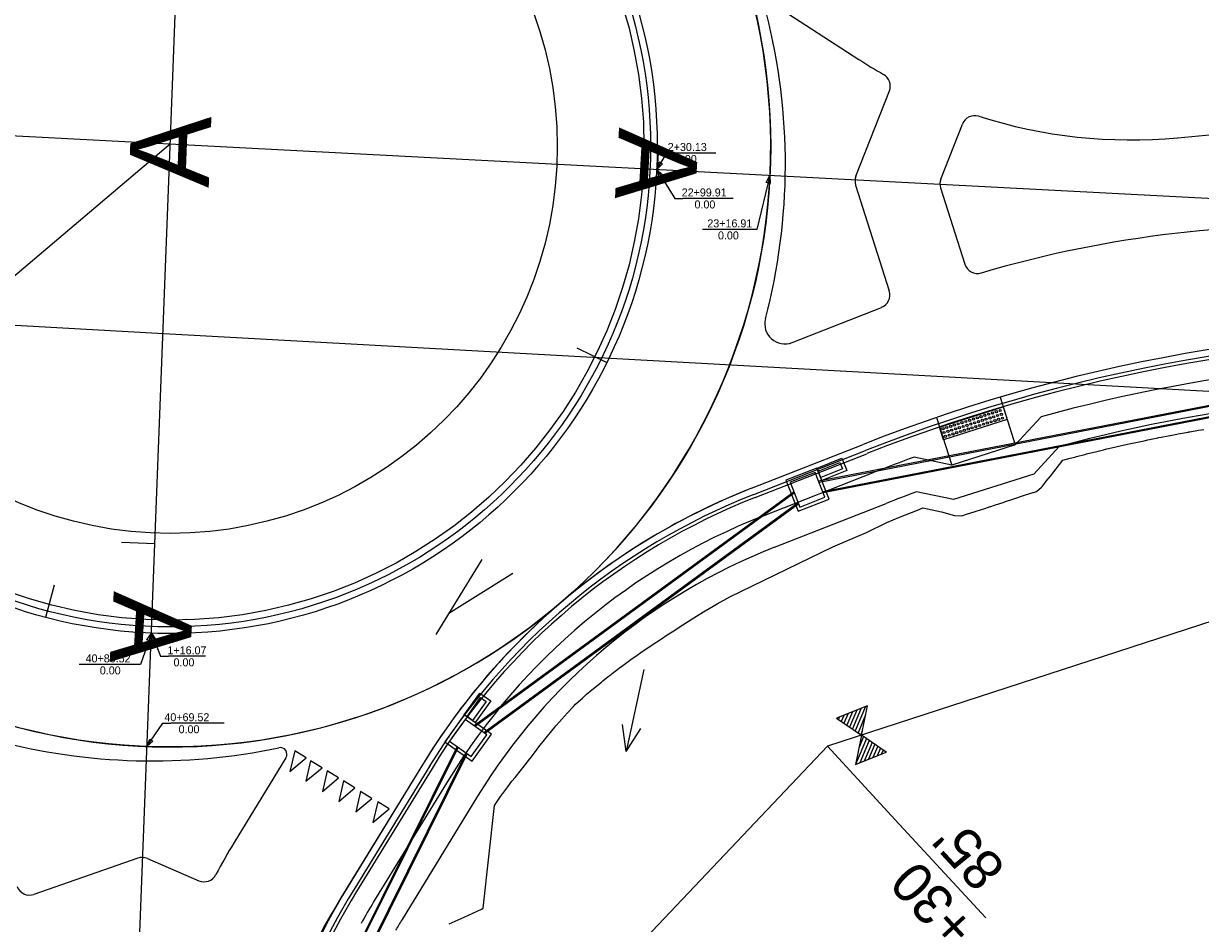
# Model space of a CAD drawing. Extents: x 670017 to 673226, y 705371 to 707498.
# Drawn here: x 671704.7 to 671881.1, y 706424.9 to 706559.8 of the extents above; entities that cross this region are included whole.
import ezdxf

# ---------------------------------------------------------------- set-up
doc = ezdxf.new("R2010")
doc.units = 0
for name, color, linetype in [('EL R 264', 7, 'Continuous'), ('EL R SCBV', 7, 'Continuous'), ('R_Drainage Flow Lines', 7, 'Continuous'), ('R_Drainage Stage 2', 7, 'Continuous'), ('R_Fence', 7, 'Continuous'), ('R_Horz Alg', 7, 'Continuous'), ('R_Horz Alg Annot', 7, 'Continuous'), ('R_Horz Alg Station', 7, 'Continuous'), ('R_No Plot', 7, 'Continuous'), ('R_No Plot FOC', 7, 'Continuous'), ('R_Proposed Const Limits Stage 2', 7, 'Continuous'), ('R_Proposed Median', 7, 'Continuous'), ('R_Proposed RAB', 7, 'Continuous'), ('R_Proposed Road Stage 2', 7, 'Continuous'), ('R_Proposed Sidewalk Stage 2', 7, 'Continuous'), ('R_ROW', 7, 'Continuous'), ('R_ROW Annot', 7, 'Continuous'), ('R_Striping', 7, 'Continuous'), ('R_Water Annot', 7, 'Continuous'), ('S_EXIST_ROW', 7, 'Continuous')]:
    doc.layers.add(name, color=color, linetype=linetype)

# ---------------------------------------------------------------- blocks, each defined once
blk = doc.blocks.new('FLOW ARROW')
at = {"layer": 'R_Water Annot'}
for p, q in [((-12.57, 0), (0, 0)), ((0, 0), (-3.85, 1.4)), ((0, 0), (-3.85, -1.4))]:
    blk.add_line(p, q, dxfattribs=at)

msp = doc.modelspace()

# ---------------------------------------------------------------- linework, layer by layer
at = {"layer": 'EL R 264'}
msp.add_line((671813.85, 706490.13), (671830.58, 706496.71), dxfattribs=at)
for centre, radius, start, end in [((671922.4, 706263.11), 251, 86.9958, 111.4581), ((671850.79, 706396.13), 101, 111.4581, 130.4404), ((671726.73, 706541.35), 90, 220.3024, 310.6243)]:
    msp.add_arc(centre, radius, start, end, dxfattribs=at)
at = {"layer": 'EL R SCBV'}
msp.add_line((671764.69, 706448.93), (671752.31, 706428.73), dxfattribs=at)
for centre, radius, start, end in [((671726.73, 706541.35), 90, 310.6243, 44.214), ((671850.79, 706396.13), 101, 130.4078, 148.4842), ((671838.41, 706375.93), 101, 148.4842, 177.7825)]:
    msp.add_arc(centre, radius, start, end, dxfattribs=at)
at = {"layer": 'R_Drainage Stage 2'}
for p, q in [((671926.49, 706511.08), (671823.91, 706491.17)), ((671926.48, 706510.91), (671823.97, 706491.01)), ((671926.45, 706509.38), (671824.53, 706489.59)), ((671926.44, 706509.2), (671824.59, 706489.44)), ((671820.24, 706489.58), (671772.3, 706454.51)), ((671820.3, 706489.42), (671772.44, 706454.41)), ((671820.87, 706487.97), (671773.73, 706453.49)), ((671820.93, 706487.81), (671773.87, 706453.39)), ((671769.73, 706451.43), (671743.1, 706397.91)), ((671769.86, 706451.33), (671743.27, 706397.88)), ((671771.1, 706450.45), (671744.8, 706397.59)), ((671771.24, 706450.35), (671744.97, 706397.56))]:
    msp.add_line(p, q, dxfattribs=at)
for points in [[(671823.66, 706493.16), (671819.01, 706491.33), (671820.84, 706486.68), (671825.49, 706488.5)], [(671823.67, 706493.16), (671827.38, 706494.64), (671828.12, 706492.78), (671824.4, 706491.3)], [(671823.85, 706492.69), (671827.1, 706493.99), (671827.47, 706493.06), (671824.22, 706491.76)], [(671823.38, 706492.51), (671819.66, 706491.05), (671821.12, 706487.32), (671824.84, 706488.79)], [(671770.8, 706456.19), (671773.13, 706459.44), (671774.76, 706458.28), (671772.43, 706455.03)], [(671771.21, 706455.9), (671773.25, 706458.75), (671774.06, 706458.16), (671772.02, 706455.32)], [(671770.8, 706456.19), (671767.9, 706452.12), (671771.97, 706449.22), (671774.87, 706453.29)], [(671770.92, 706455.49), (671768.59, 706452.24), (671771.85, 706449.92), (671774.17, 706453.17)]]:
    msp.add_lwpolyline(points, close=True, dxfattribs=at)
at = {"layer": 'R_Fence'}
for p, q in [((671827.67, 706456.09), (671827.29, 706455.19)), ((671828.32, 706456.36), (671827.71, 706454.91)), ((671828.98, 706456.62), (671828.13, 706454.62)), ((671829.63, 706456.89), (671828.55, 706454.33)), ((671830.29, 706457.15), (671828.97, 706454.05)), ((671830.94, 706457.42), (671829.39, 706453.76)), ((671830.95, 706456.16), (671829.82, 706453.47)), ((671827.01, 706455.82), (671826.87, 706455.48)), ((671831.08, 706452.61), (671829.43, 706448.71)), ((671830.66, 706452.9), (671829.93, 706451.16)), ((671831.5, 706452.32), (671830.09, 706448.98)), ((671830.44, 706453.66), (671830.24, 706453.18)), ((671831.92, 706452.04), (671830.74, 706449.24)), ((671832.35, 706451.75), (671831.4, 706449.51)), ((671832.77, 706451.46), (671832.05, 706449.77)), ((671833.19, 706451.18), (671832.71, 706450.04)), ((671833.61, 706450.89), (671833.36, 706450.31)), ((671834.03, 706450.6), (671834.02, 706450.57))]:
    msp.add_line(p, q, dxfattribs=at)
msp.add_lwpolyline([(671830.34, 706453.12), (671830.33, 706453.13), (671831.24, 706457.54), (671826.6, 706455.66), (671830.32, 706453.13), (671830.33, 706453.11), (671829.42, 706448.71), (671834.05, 706450.59), (671830.34, 706453.12)], dxfattribs=at)
at = {"layer": 'R_Horz Alg'}
for p, q in [((671726.73, 706541.35), (671758.33, 707389.39)), ((670501.52, 706606.05), (672734.79, 706488.84)), ((671681.86, 705382.69), (671726.73, 706541.35))]:
    msp.add_line(p, q, dxfattribs=at)
msp.add_circle((671726.73, 706541.35), 73, dxfattribs=at)
at = {"layer": 'R_Horz Alg Annot'}
msp.add_line((671726.74, 706541.74), (671559.77, 706400.21), dxfattribs=at)
at = {"layer": 'R_Horz Alg Station'}
for points in [[(671799.86, 706540.41), (671799.73, 706537.91)], [(671787.67, 706511.18), (671792.15, 706508.96)], [(671719.43, 706482.06), (671724.42, 706481.87)], [(671721.92, 706481.97), (671724.42, 706481.87)], [(671709.32, 706475.61), (671708.04, 706470.78)]]:
    msp.add_lwpolyline(points, dxfattribs=at)
at = {"layer": 'R_No Plot'}
for p, q in [((671808.5, 706540.38), (671802.34, 706540.38)), ((671811.12, 706533.57), (671803.58, 706533.57)), ((671813.45, 706528.93), (671806.53, 706528.93)), ((671773.44, 706479.45), (671766.53, 706468.19)), ((671778.06, 706477.35), (671768.47, 706471.35)), ((671731.99, 706464.94), (671726.45, 706464.94)), ((671721.06, 706463.73), (671713.08, 706463.73)), ((671734.81, 706454.91), (671726.83, 706454.91))]:
    msp.add_line(p, q, dxfattribs=at)
for points in [[(671799.64, 706537.92), (671801.14, 706540.38), (671802.34, 706540.38)], [(671799.64, 706537.92), (671802.38, 706533.57), (671803.58, 706533.57)], [(671816.62, 706537.03), (671814.65, 706528.93), (671813.45, 706528.93)], [(671723.9, 706468.4), (671722.26, 706463.73), (671721.06, 706463.73)], [(671723.9, 706468.4), (671725.25, 706464.94), (671726.45, 706464.94)], [(671723.24, 706451.42), (671725.63, 706454.91), (671726.83, 706454.91)]]:
    msp.add_lwpolyline(points, dxfattribs=at)
for points in [[(671799.64, 706537.92), (671800, 706539.06), (671800.5, 706538.76)], [(671799.64, 706537.92), (671800.51, 706537.09), (671800.02, 706536.78)], [(671816.62, 706537.03), (671816.63, 706535.83), (671816.06, 706535.96)], [(671723.9, 706468.4), (671723.79, 706467.21), (671723.24, 706467.4)], [(671723.9, 706468.4), (671724.59, 706467.42), (671724.05, 706467.21)], [(671723.24, 706451.42), (671723.66, 706452.54), (671724.14, 706452.21)]]:
    msp.add_lwpolyline(points, close=True, dxfattribs=at)
msp.add_circle((671726.73, 706541.35), 90, dxfattribs=at)
at = {"layer": 'R_No Plot FOC'}
for p, q in [((671814.21, 706489.2), (671830.94, 706495.78)), ((671765.64, 706448.55), (671754.23, 706429.95))]:
    msp.add_line(p, q, dxfattribs=at)
msp.add_circle((671726.73, 706541.35), 72, dxfattribs=at)
for centre, radius, start, end in [((671922.4, 706263.11), 250, 86.9958, 111.4581), ((671850.79, 706396.13), 100, 111.4581, 148.4842), ((671839.48, 706377.68), 100, 148.4842, 177.7825)]:
    msp.add_arc(centre, radius, start, end, dxfattribs=at)
at = {"layer": 'R_Proposed Const Limits Stage 2'}
for points in [[(671860.54, 706494.34), (671861.63, 706494.63), (671862.3, 706494.81), (671862.56, 706494.88), (671863.83, 706495.21), (671864.08, 706495.27), (671865.61, 706495.65), (671866.03, 706495.76), (671866.63, 706495.9), (671867.13, 706496.03), (671868.25, 706496.29), (671868.66, 706496.38), (671870.19, 706496.72), (671870.47, 706496.79), (671870.95, 706496.89), (671871.71, 706497.06), (671872.69, 706497.26), (671873.24, 706497.38), (671874.77, 706497.69), (671874.93, 706497.72), (671875.26, 706497.79), (671876.29, 706497.99), (671877.16, 706498.16), (671877.81, 706498.28), (671879.32, 706498.55), (671879.41, 706498.57), (671879.57, 706498.6), (671880.83, 706498.82), (671881.66, 706498.96)], [(671839.51, 706487.21), (671842.33, 706486.59), (671844.28, 706486.07), (671845.37, 706485.99), (671845.38, 706485.99), (671845.94, 706486.18), (671847.37, 706486.64), (671847.51, 706486.69), (671848.82, 706487.11), (671849.64, 706487.38), (671849.73, 706487.41), (671850.26, 706487.59), (671851.72, 706488.06), (671851.78, 706488.08), (671853.18, 706488.54), (671853.91, 706488.78), (671854.03, 706488.82), (671854.64, 706489.02), (671855.74, 706489.38), (671856.03, 706489.48), (671856.11, 706489.5), (671856.59, 706489.66), (671857.33, 706490.31), (671857.45, 706490.46), (671857.92, 706491.05), (671858.01, 706491.17), (671858.65, 706491.96), (671860.54, 706494.34)], [(671826.03, 706481.35), (671828.14, 706482.26), (671831.09, 706483.51), (671834.14, 706485), (671836.03, 706485.79), (671838.74, 706486.86), (671839.51, 706487.21)], [(671768.51, 706424.84), (671770.76, 706425.83), (671773.39, 706427.05), (671773.63, 706427.17), (671775.31, 706442.6), (671776.25, 706443.94), (671776.52, 706444.32), (671776.56, 706444.37), (671777.31, 706445.38), (671777.95, 706446.21), (671778.41, 706446.79), (671779.37, 706447.98), (671779.53, 706448.18), (671779.59, 706448.25), (671780.63, 706449.59), (671780.64, 706449.6), (671780.71, 706449.69), (671781.7, 706451.01), (671781.98, 706451.37), (671782.8, 706452.41), (671783.26, 706452.97), (671783.93, 706453.79), (671784.37, 706454.3), (671784.54, 706454.5), (671785.09, 706455.14), (671785.83, 706455.98), (671786.28, 706456.48), (671787.12, 706457.39), (671787.49, 706457.79), (671788.2, 706458.43), (671788.5, 706458.69), (671788.83, 706458.97), (671789.08, 706459.2), (671789.93, 706459.91), (671790.19, 706460.13), (671791.36, 706461.09), (671791.57, 706461.25), (671792.39, 706461.91), (671792.81, 706462.23), (671792.97, 706462.36), (671794.27, 706463.35), (671794.38, 706463.43), (671795.75, 706464.44), (671796.7, 706465.12), (671797.26, 706465.51), (671798.79, 706466.55), (671800.35, 706467.58), (671801.23, 706468.15), (671801.95, 706468.6), (671803.55, 706469.67), (671805.21, 706470.72), (671806.02, 706471.22), (671806.93, 706471.77), (671808.72, 706472.83), (671810.58, 706473.88), (671826.03, 706481.35)]]:
    msp.add_lwpolyline(points, dxfattribs=at)
at = {"layer": 'R_Proposed Median'}
for p, q in [((671817.61, 706562.4), (671829.92, 706554.42)), ((671829.51, 706536.9), (671834.52, 706549.68)), ((671877.73, 706542.67), (671931.12, 706547.67)), ((671842.23, 706536.48), (671845.46, 706544.71)), ((671829.46, 706535.56), (671834.5, 706519.71)), ((671842.19, 706535.14), (671845.82, 706523.71)), ((671819.94, 706511.98), (671833.33, 706517.24)), ((671744.07, 706449.74), (671736.29, 706437.04)), ((671721.85, 706434.7), (671706.29, 706429.26)), ((671723.31, 706434.65), (671731, 706431.31))]:
    msp.add_line(p, q, dxfattribs=at)
for centre, radius, start, end in [((671727.43, 706538.73), 91.5, 345.3135, 14.2896), ((671870.73, 706617.34), 75, 237.03, 240.3633), ((671832.66, 706550.41), 2, 338.5828, 60.3633), ((671847.32, 706543.98), 2, 72.2997, 158.5828), ((671870.73, 706617.34), 75, 252.2997, 275.3546), ((671831.37, 706536.17), 2, 158.5828, 197.6402), ((671844.09, 706535.75), 2, 158.5828, 197.6402), ((671897.73, 706354.52), 175, 86.9958, 106.4093), ((671847.73, 706524.32), 2, 197.6402, 286.4093), ((671832.6, 706519.11), 2, 291.4581, 17.6402), ((671818.84, 706514.77), 3, 165.3135, 291.4581), ((671724.07, 706540.76), 91.5, 254.9886, 281.9484), ((671743.22, 706450.26), 1, 328.4842, 101.9484), ((671800.23, 706397.84), 75, 148.4842, 152.711), ((671722.51, 706432.81), 2, 66.5337, 109.2743), ((671731.8, 706433.14), 2, 246.5337, 332.711), ((671705.63, 706431.15), 2, 201.1999, 289.2743)]:
    msp.add_arc(centre, radius, start, end, dxfattribs=at)
at = {"layer": 'R_Proposed RAB'}
for radius in [71, 58]:
    msp.add_circle((671726.73, 706541.35), radius, dxfattribs=at)
at = {"layer": 'R_Proposed Road Stage 2'}
for p, q in [((671813.85, 706490.13), (671830.58, 706496.71)), ((671814.4, 706488.74), (671831.13, 706495.31)), ((671764.69, 706448.93), (671753.37, 706430.47)), ((671765.97, 706448.15), (671754.65, 706429.69))]:
    msp.add_line(p, q, dxfattribs=at)
for centre, radius, start, end in [((671922.4, 706263.11), 251, 86.9958, 111.4581), ((671922.4, 706263.11), 249.5, 86.9958, 111.4581), ((671850.79, 706396.13), 101, 111.4581, 148.4842), ((671850.79, 706396.13), 99.5, 111.4581, 148.4842), ((671839.48, 706377.68), 101, 148.4842, 177.7825), ((671839.48, 706377.68), 99.5, 148.4842, 177.7825)]:
    msp.add_arc(centre, radius, start, end, dxfattribs=at)
at = {"layer": 'R_Proposed Sidewalk Stage 2'}
for p, q in [((671851.11, 706503.77), (671853.39, 706496.62)), ((671841.59, 706500.74), (671843.86, 706493.59)), ((671852.18, 706500.44), (671842.65, 706497.41)), ((671853.39, 706496.62), (671857.29, 706500.85)), ((671853.39, 706496.62), (671843.86, 706493.59)), ((671843.86, 706493.59), (671838.23, 706494.79)), ((671856.16, 706492.26), (671859.99, 706496.4)), ((671815.49, 706485.94), (671832.22, 706492.52)), ((671856.16, 706492.26), (671844.11, 706488.43)), ((671844.11, 706488.43), (671838.6, 706489.6)), ((671817.32, 706481.29), (671834.05, 706487.87)), ((671768.53, 706446.58), (671757.21, 706428.12)), ((671772.79, 706443.96), (671761.47, 706425.51))]:
    msp.add_line(p, q, dxfattribs=at)
msp.add_lwpolyline([(671842.04, 706499.31), (671851.57, 706502.34), (671852.18, 706500.44), (671842.65, 706497.41)], close=True, dxfattribs=at)
for centre in [(671850.55, 706501.6), (671851.12, 706501.78), (671845.4, 706499.96), (671845.97, 706500.14), (671846.54, 706500.32), (671847.12, 706500.51), (671847.3, 706499.93), (671847.69, 706500.69), (671847.87, 706500.12), (671848.26, 706500.87), (671848.44, 706500.3), (671848.83, 706501.05), (671849.01, 706500.48), (671849.2, 706499.91), (671849.4, 706501.23), (671849.59, 706500.66), (671849.77, 706500.09), (671849.98, 706501.42), (671850.16, 706500.84), (671850.34, 706500.27), (671850.73, 706501.03), (671850.91, 706500.45), (671851.3, 706501.21), (671851.48, 706500.64), (671842.54, 706499.05), (671842.72, 706498.48), (671843.11, 706499.23), (671843.3, 706498.66), (671843.48, 706498.09), (671843.69, 706499.42), (671843.87, 706498.84), (671844.05, 706498.27), (671844.26, 706499.6), (671844.44, 706499.03), (671844.62, 706498.45), (671844.83, 706499.78), (671845.01, 706499.21), (671845.19, 706498.64), (671845.58, 706499.39), (671845.76, 706498.82), (671846.15, 706499.57), (671846.34, 706499), (671846.73, 706499.75), (671846.91, 706499.18), (671847.48, 706499.36), (671848.05, 706499.54), (671848.62, 706499.73), (671842.91, 706497.91)]:
    msp.add_circle(centre, 0.165, dxfattribs=at)
for centre, radius, start, end in [((671922.4, 706263.11), 246.5, 86.9958, 105.3152), ((671922.4, 706263.11), 241.5, 86.9958, 104.9768), ((671922.4, 706263.11), 246.5, 109.9652, 111.4581), ((671922.4, 706263.11), 241.5, 110.3036, 111.4581), ((671850.79, 706396.13), 96.5, 111.4581, 148.4842), ((671850.79, 706396.13), 91.5, 111.4581, 148.4842), ((671839.48, 706377.68), 96.5, 148.4842, 150.7012), ((671839.48, 706377.68), 91.5, 148.4842, 149.6675)]:
    msp.add_arc(centre, radius, start, end, dxfattribs=at)
at = {"layer": 'R_ROW'}
msp.add_lwpolyline([(672596.28, 706451.05), (672596.28, 706451.05), (672161.7, 706463.84), (671891.46, 706473.02), (671825.24, 706451.46), (671776.29, 706399.8), (671754.1, 706085.43), (671832.11, 706032.37), (671817.47, 705912.84), (671726.19, 705881.35)], dxfattribs=at)
at = {"layer": 'R_ROW Annot'}
msp.add_lwpolyline([(671825.24, 706451.46), (671835.41, 706440.43), (671848.97, 706425.74)], dxfattribs=at)
at = {"layer": 'R_Striping'}
for points in [[(671747.09, 706449.7), (671745.39, 706450.75), (671744.67, 706447.67), (671747.09, 706449.7)], [(671745.39, 706450.75), (671744.67, 706447.67)], [(671744.67, 706447.67), (671747.09, 706449.7)], [(671749.48, 706448.24), (671747.77, 706449.29), (671747.05, 706446.21), (671749.48, 706448.24)], [(671747.77, 706449.29), (671747.05, 706446.21)], [(671747.05, 706446.21), (671749.48, 706448.24)], [(671749.53, 706444.69), (671751.95, 706446.72), (671750.25, 706447.77), (671749.53, 706444.69)], [(671750.25, 706447.77), (671749.53, 706444.69)], [(671749.53, 706444.69), (671751.95, 706446.72)], [(671754.41, 706445.21), (671752.7, 706446.26), (671751.98, 706443.18), (671754.41, 706445.21)], [(671752.7, 706446.26), (671751.98, 706443.18)], [(671751.98, 706443.18), (671754.41, 706445.21)], [(671755.26, 706444.69), (671754.54, 706441.61)], [(671756.96, 706443.64), (671755.26, 706444.69), (671754.54, 706441.61), (671756.96, 706443.64)], [(671754.54, 706441.61), (671756.96, 706443.64)], [(671759.52, 706442.07), (671757.82, 706443.12), (671757.1, 706440.04), (671759.52, 706442.07)], [(671757.82, 706443.12), (671757.1, 706440.04)], [(671757.1, 706440.04), (671759.52, 706442.07)]]:
    msp.add_lwpolyline(points, dxfattribs=at)
at = {"layer": 'S_EXIST_ROW'}
msp.add_lwpolyline([(670017.21, 706598.61), (670616.41, 706569.67), (670616.54, 706574.67), (671724.85, 706513.39), (673222.56, 706430.57)], dxfattribs=at)

# ---------------------------------------------------------------- block references
at = {"layer": 'R_Drainage Flow Lines', "rotation": -102.3404751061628}
msp.add_blockref('FLOW ARROW', (671795.05, 706450.66), dxfattribs=at)

# ---------------------------------------------------------------- texts
at = {"layer": 'R_Horz Alg'}
for rotation, p in [(87.8241, (671732.49, 706535.13)), (266.6859, (671794, 706544.25)), (266.6859, (671718.26, 706474.74))]:
    msp.add_text('A', height=12, rotation=rotation, dxfattribs=at).set_placement(p)
at = {"layer": 'R_No Plot'}
for s, p in [('2+30.13', (671801.3, 706540.68)), ('0.00', (671802.52, 706538.88)), ('22+99.91', (671803.39, 706533.87)), ('0.00', (671805.31, 706532.07)), ('23+16.91', (671807.23, 706529.23)), ('0.00', (671808.83, 706527.43)), ('1+16.07', (671726.31, 706465.24)), ('40+86.52', (671714.04, 706464.03)), ('0.00', (671716.17, 706462.23)), ('0.00', (671727.22, 706463.44)), ('40+69.52', (671725.85, 706455.21)), ('0.00', (671727.98, 706453.41))]:
    msp.add_text(s, height=1.2, rotation=360, dxfattribs=at).set_placement(p)
at = {"layer": 'R_ROW Annot'}
for s, p in [("85'", (671852.17, 706433.34)), ('+30', (671847.9, 706424.69))]:
    msp.add_text(s, height=6, rotation=132.7034, dxfattribs=at).set_placement(p)

doc.saveas('drawing.dxf')
